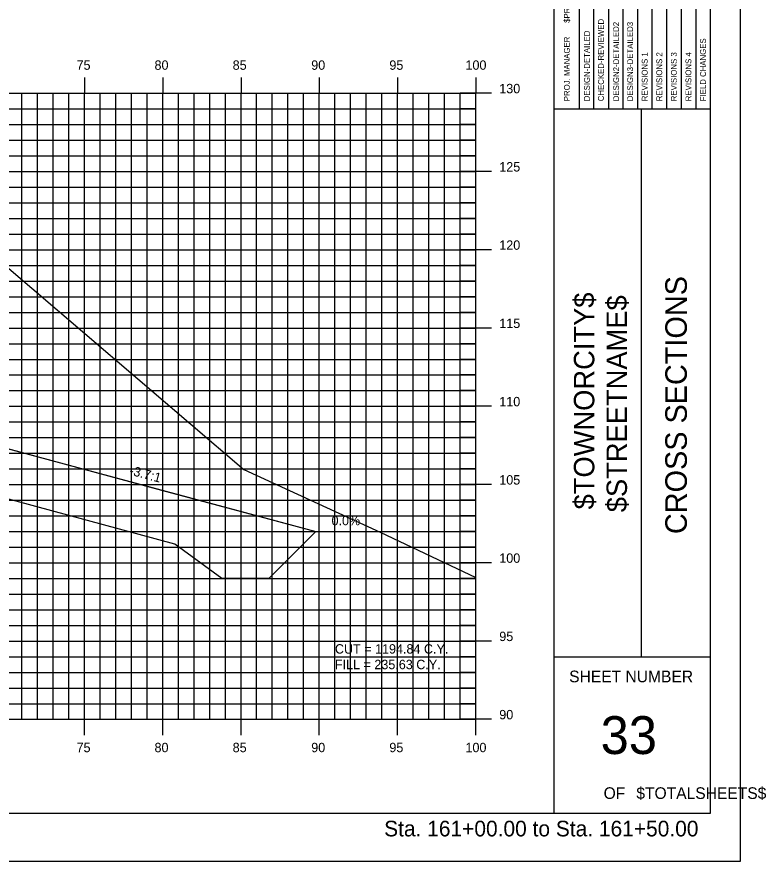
# Model space of a CAD drawing. Extents: x 850598 to 870284, y 366541 to 366651.
# Drawn here: x 853826.2 to 853874, y 366541.2 to 366595.1 of the extents above; entities that cross this region are included whole.
import ezdxf

# ---------------------------------------------------------------- set-up
doc = ezdxf.new("R2010")
doc.units = 0
for name, color, linetype in [('ANNOTATION', 7, 'Continuous'), ('BORDER', 7, 'Continuous'), ('D_Drainage_RipRap', 7, 'Continuous'), ('D_Roadway_Centerline', 7, 'Continuous'), ('D_Roadway_SlopeLines', 7, 'Continuous'), ('D_Text_Standard', 7, 'Continuous'), ('H_V ANNOTATION', 7, 'Continuous'), ('HIGHWAY_TITLE', 7, 'Continuous'), ('MAJOR', 7, 'Continuous'), ('MINOR', 7, 'Continuous'), ('PLOT BOUNDARY', 7, 'Continuous'), ('S_Roadway_Centerline', 7, 'Continuous')]:
    doc.layers.add(name, color=color, linetype=linetype)

msp = doc.modelspace()

# ---------------------------------------------------------------- linework, layer by layer
at = {"layer": 'BORDER'}
for p, q in [((853860.489, 366544.225), (853860.489, 366649.225)), ((853870.489, 366544.225), (853870.489, 366649.225)), ((853860.489, 366589.228), (853870.489, 366589.228)), ((853866.08, 366554.228), (853866.08, 366589.228)), ((853860.489, 366554.228), (853870.489, 366554.228)), ((853710.489, 366544.225), (853870.489, 366544.225))]:
    msp.add_line(p, q, dxfattribs=at)
for points in [[(853863.036, 366589.231), (853863.036, 366606.728)], [(853863.968, 366606.728), (853863.968, 366589.231)], [(853864.9, 366589.231), (853864.9, 366606.728)], [(853865.831, 366589.231), (853865.831, 366606.728)], [(853866.763, 366589.231), (853866.763, 366606.728)], [(853867.695, 366589.231), (853867.695, 366606.728)], [(853868.626, 366589.231), (853868.626, 366606.728)], [(853869.558, 366589.231), (853869.558, 366606.728)], [(853862.105, 366589.231), (853862.105, 366606.022)]]:
    msp.add_lwpolyline(points, dxfattribs=at)
at = {"layer": 'D_Drainage_RipRap'}
msp.add_lwpolyline([(853822.953, 366568.225), (853835.405, 366564.877), (853845.267, 366562.225), (853842.267, 366559.225), (853839.267, 366559.225), (853836.267, 366561.427), (853823.815, 366564.775), (853822.953, 366566.725), (853778.489, 366578.682), (853778.489, 366580.182)], close=True, dxfattribs=at)
at = {"layer": 'D_Roadway_Centerline'}
msp.add_lwpolyline([(853725.548, 366577.322), (853730.489, 366578.969), (853734.291, 366580.236), (853740.489, 366582.302), (853744.489, 366582.542), (853755.489, 366582.872), (853766.489, 366582.542), (853770.489, 366582.302), (853772.489, 366582.182), (853778.489, 366580.182), (853822.953, 366568.225), (853835.405, 366564.877), (853845.267, 366562.225), (853849.267, 366562.225)], dxfattribs=at)
at = {"layer": 'D_Roadway_SlopeLines'}
msp.add_lwpolyline([(853778.489, 366580.182), (853845.267, 366562.225), (853845.267, 366562.225)], dxfattribs=at)
at = {"layer": 'MAJOR'}
for p, q in [((853830.489, 366591.227), (853830.489, 366590.225)), ((853830.489, 366591.227), (853830.489, 366590.225)), ((853835.489, 366591.227), (853835.489, 366590.225)), ((853835.489, 366591.227), (853835.489, 366590.225)), ((853840.489, 366591.227), (853840.489, 366590.225)), ((853840.489, 366591.227), (853840.489, 366590.225)), ((853845.489, 366591.227), (853845.489, 366590.225)), ((853845.489, 366591.227), (853845.489, 366590.225)), ((853850.489, 366591.227), (853850.489, 366590.225)), ((853850.489, 366591.227), (853850.489, 366590.225)), ((853855.489, 366591.227), (853855.489, 366590.225)), ((853855.489, 366591.227), (853855.489, 366590.225)), ((853715.489, 366590.225), (853855.489, 366590.225)), ((853715.489, 366590.225), (853855.489, 366590.225)), ((853715.489, 366590.225), (853855.489, 366590.225)), ((853715.489, 366590.225), (853855.489, 366590.225)), ((853830.489, 366550.225), (853830.489, 366590.225)), ((853830.489, 366550.225), (853830.489, 366590.225)), ((853835.489, 366550.225), (853835.489, 366590.225)), ((853835.489, 366550.225), (853835.489, 366590.225)), ((853840.489, 366550.225), (853840.489, 366590.225)), ((853840.489, 366550.225), (853840.489, 366590.225)), ((853845.489, 366550.225), (853845.489, 366590.225)), ((853845.489, 366550.225), (853845.489, 366590.225)), ((853850.489, 366550.225), (853850.489, 366590.225)), ((853850.489, 366550.225), (853850.489, 366590.225)), ((853856.491, 366590.225), (853854.487, 366590.225)), ((853856.491, 366590.225), (853854.487, 366590.225)), ((853855.489, 366550.225), (853855.489, 366590.225)), ((853855.489, 366550.225), (853855.489, 366590.225)), ((853855.489, 366550.225), (853855.489, 366590.225)), ((853855.489, 366550.225), (853855.489, 366590.225)), ((853715.489, 366585.225), (853855.489, 366585.225)), ((853715.489, 366585.225), (853855.489, 366585.225)), ((853856.491, 366585.225), (853854.487, 366585.225)), ((853856.491, 366585.225), (853854.487, 366585.225)), ((853715.489, 366580.225), (853855.489, 366580.225)), ((853715.489, 366580.225), (853855.489, 366580.225)), ((853856.491, 366580.225), (853854.487, 366580.225)), ((853856.491, 366580.225), (853854.487, 366580.225)), ((853715.489, 366575.225), (853855.489, 366575.225)), ((853715.489, 366575.225), (853855.489, 366575.225)), ((853856.491, 366575.225), (853854.487, 366575.225)), ((853856.491, 366575.225), (853854.487, 366575.225)), ((853715.489, 366570.225), (853855.489, 366570.225)), ((853715.489, 366570.225), (853855.489, 366570.225)), ((853856.491, 366570.225), (853854.487, 366570.225)), ((853856.491, 366570.225), (853854.487, 366570.225)), ((853715.489, 366565.225), (853855.489, 366565.225)), ((853715.489, 366565.225), (853855.489, 366565.225)), ((853856.491, 366565.225), (853854.487, 366565.225)), ((853856.491, 366565.225), (853854.487, 366565.225)), ((853715.489, 366560.225), (853855.489, 366560.225)), ((853715.489, 366560.225), (853855.489, 366560.225)), ((853856.491, 366560.225), (853854.487, 366560.225)), ((853856.491, 366560.225), (853854.487, 366560.225)), ((853715.489, 366555.225), (853855.489, 366555.225)), ((853715.489, 366555.225), (853855.489, 366555.225)), ((853856.491, 366555.225), (853854.487, 366555.225)), ((853856.491, 366555.225), (853854.487, 366555.225)), ((853715.489, 366550.225), (853855.489, 366550.225)), ((853715.489, 366550.225), (853855.489, 366550.225)), ((853715.489, 366550.225), (853855.489, 366550.225)), ((853715.489, 366550.225), (853855.489, 366550.225)), ((853830.489, 366549.223), (853830.489, 366550.225)), ((853830.489, 366549.223), (853830.489, 366550.225)), ((853835.489, 366549.223), (853835.489, 366550.225)), ((853835.489, 366549.223), (853835.489, 366550.225)), ((853840.489, 366549.223), (853840.489, 366550.225)), ((853840.489, 366549.223), (853840.489, 366550.225)), ((853845.489, 366549.223), (853845.489, 366550.225)), ((853845.489, 366549.223), (853845.489, 366550.225)), ((853850.489, 366549.223), (853850.489, 366550.225)), ((853850.489, 366549.223), (853850.489, 366550.225)), ((853856.491, 366550.225), (853854.487, 366550.225)), ((853856.491, 366550.225), (853854.487, 366550.225)), ((853855.489, 366549.223), (853855.489, 366550.225)), ((853855.489, 366549.223), (853855.489, 366550.225))]:
    msp.add_line(p, q, dxfattribs=at)
at = {"layer": 'MINOR'}
for p, q in [((853826.489, 366550.225), (853826.489, 366590.225)), ((853826.489, 366550.225), (853826.489, 366590.225)), ((853827.489, 366550.225), (853827.489, 366590.225)), ((853827.489, 366550.225), (853827.489, 366590.225)), ((853828.489, 366550.225), (853828.489, 366590.225)), ((853828.489, 366550.225), (853828.489, 366590.225)), ((853829.489, 366550.225), (853829.489, 366590.225)), ((853829.489, 366550.225), (853829.489, 366590.225)), ((853831.489, 366550.225), (853831.489, 366590.225)), ((853831.489, 366550.225), (853831.489, 366590.225)), ((853832.489, 366550.225), (853832.489, 366590.225)), ((853832.489, 366550.225), (853832.489, 366590.225)), ((853833.489, 366550.225), (853833.489, 366590.225)), ((853833.489, 366550.225), (853833.489, 366590.225)), ((853834.489, 366550.225), (853834.489, 366590.225)), ((853834.489, 366550.225), (853834.489, 366590.225)), ((853836.489, 366550.225), (853836.489, 366590.225)), ((853836.489, 366550.225), (853836.489, 366590.225)), ((853837.489, 366550.225), (853837.489, 366590.225)), ((853837.489, 366550.225), (853837.489, 366590.225)), ((853838.489, 366550.225), (853838.489, 366590.225)), ((853838.489, 366550.225), (853838.489, 366590.225)), ((853839.489, 366550.225), (853839.489, 366590.225)), ((853839.489, 366550.225), (853839.489, 366590.225)), ((853841.489, 366550.225), (853841.489, 366590.225)), ((853841.489, 366550.225), (853841.489, 366590.225)), ((853842.489, 366550.225), (853842.489, 366590.225)), ((853842.489, 366550.225), (853842.489, 366590.225)), ((853843.489, 366550.225), (853843.489, 366590.225)), ((853843.489, 366550.225), (853843.489, 366590.225)), ((853844.489, 366550.225), (853844.489, 366590.225)), ((853844.489, 366550.225), (853844.489, 366590.225)), ((853846.489, 366550.225), (853846.489, 366590.225)), ((853846.489, 366550.225), (853846.489, 366590.225)), ((853847.489, 366550.225), (853847.489, 366590.225)), ((853847.489, 366550.225), (853847.489, 366590.225)), ((853848.489, 366550.225), (853848.489, 366590.225)), ((853848.489, 366550.225), (853848.489, 366590.225)), ((853849.489, 366550.225), (853849.489, 366590.225)), ((853849.489, 366550.225), (853849.489, 366590.225)), ((853851.489, 366550.225), (853851.489, 366590.225)), ((853851.489, 366550.225), (853851.489, 366590.225)), ((853852.489, 366550.225), (853852.489, 366590.225)), ((853852.489, 366550.225), (853852.489, 366590.225)), ((853853.489, 366550.225), (853853.489, 366590.225)), ((853853.489, 366550.225), (853853.489, 366590.225)), ((853854.489, 366550.225), (853854.489, 366590.225)), ((853854.489, 366550.225), (853854.489, 366590.225)), ((853715.489, 366589.225), (853855.489, 366589.225)), ((853715.489, 366589.225), (853855.489, 366589.225)), ((853855.489, 366589.225), (853854.487, 366589.225)), ((853855.489, 366589.225), (853854.487, 366589.225)), ((853715.489, 366588.225), (853855.489, 366588.225)), ((853715.489, 366588.225), (853855.489, 366588.225)), ((853855.489, 366588.225), (853854.487, 366588.225)), ((853855.489, 366588.225), (853854.487, 366588.225)), ((853715.489, 366587.225), (853855.489, 366587.225)), ((853715.489, 366587.225), (853855.489, 366587.225)), ((853855.489, 366587.225), (853854.487, 366587.225)), ((853855.489, 366587.225), (853854.487, 366587.225)), ((853715.489, 366586.225), (853855.489, 366586.225)), ((853715.489, 366586.225), (853855.489, 366586.225)), ((853855.489, 366586.225), (853854.487, 366586.225)), ((853855.489, 366586.225), (853854.487, 366586.225)), ((853715.489, 366584.225), (853855.489, 366584.225)), ((853715.489, 366584.225), (853855.489, 366584.225)), ((853855.489, 366584.225), (853854.487, 366584.225)), ((853855.489, 366584.225), (853854.487, 366584.225)), ((853715.489, 366583.225), (853855.489, 366583.225)), ((853715.489, 366583.225), (853855.489, 366583.225)), ((853855.489, 366583.225), (853854.487, 366583.225)), ((853855.489, 366583.225), (853854.487, 366583.225)), ((853715.489, 366582.225), (853855.489, 366582.225)), ((853715.489, 366582.225), (853855.489, 366582.225)), ((853855.489, 366582.225), (853854.487, 366582.225)), ((853855.489, 366582.225), (853854.487, 366582.225)), ((853715.489, 366581.225), (853855.489, 366581.225)), ((853715.489, 366581.225), (853855.489, 366581.225)), ((853855.489, 366581.225), (853854.487, 366581.225)), ((853855.489, 366581.225), (853854.487, 366581.225)), ((853715.489, 366579.225), (853855.489, 366579.225)), ((853715.489, 366579.225), (853855.489, 366579.225)), ((853855.489, 366579.225), (853854.487, 366579.225)), ((853855.489, 366579.225), (853854.487, 366579.225)), ((853715.489, 366578.225), (853855.489, 366578.225)), ((853715.489, 366578.225), (853855.489, 366578.225)), ((853855.489, 366578.225), (853854.487, 366578.225)), ((853855.489, 366578.225), (853854.487, 366578.225)), ((853715.489, 366577.225), (853855.489, 366577.225)), ((853715.489, 366577.225), (853855.489, 366577.225)), ((853855.489, 366577.225), (853854.487, 366577.225)), ((853855.489, 366577.225), (853854.487, 366577.225)), ((853715.489, 366576.225), (853855.489, 366576.225)), ((853715.489, 366576.225), (853855.489, 366576.225)), ((853855.489, 366576.225), (853854.487, 366576.225)), ((853855.489, 366576.225), (853854.487, 366576.225)), ((853715.489, 366574.225), (853855.489, 366574.225)), ((853715.489, 366574.225), (853855.489, 366574.225)), ((853855.489, 366574.225), (853854.487, 366574.225)), ((853855.489, 366574.225), (853854.487, 366574.225)), ((853715.489, 366573.225), (853855.489, 366573.225)), ((853715.489, 366573.225), (853855.489, 366573.225)), ((853855.489, 366573.225), (853854.487, 366573.225)), ((853855.489, 366573.225), (853854.487, 366573.225)), ((853715.489, 366572.225), (853855.489, 366572.225)), ((853715.489, 366572.225), (853855.489, 366572.225)), ((853855.489, 366572.225), (853854.487, 366572.225)), ((853855.489, 366572.225), (853854.487, 366572.225)), ((853715.489, 366571.225), (853855.489, 366571.225)), ((853715.489, 366571.225), (853855.489, 366571.225)), ((853855.489, 366571.225), (853854.487, 366571.225)), ((853855.489, 366571.225), (853854.487, 366571.225)), ((853715.489, 366569.225), (853855.489, 366569.225)), ((853715.489, 366569.225), (853855.489, 366569.225)), ((853855.489, 366569.225), (853854.487, 366569.225)), ((853855.489, 366569.225), (853854.487, 366569.225)), ((853715.489, 366568.225), (853855.489, 366568.225)), ((853715.489, 366568.225), (853855.489, 366568.225)), ((853855.489, 366568.225), (853854.487, 366568.225)), ((853855.489, 366568.225), (853854.487, 366568.225)), ((853715.489, 366567.225), (853855.489, 366567.225)), ((853715.489, 366567.225), (853855.489, 366567.225)), ((853855.489, 366567.225), (853854.487, 366567.225)), ((853855.489, 366567.225), (853854.487, 366567.225)), ((853715.489, 366566.225), (853855.489, 366566.225)), ((853715.489, 366566.225), (853855.489, 366566.225)), ((853855.489, 366566.225), (853854.487, 366566.225)), ((853855.489, 366566.225), (853854.487, 366566.225)), ((853715.489, 366564.225), (853855.489, 366564.225)), ((853715.489, 366564.225), (853855.489, 366564.225)), ((853855.489, 366564.225), (853854.487, 366564.225)), ((853855.489, 366564.225), (853854.487, 366564.225)), ((853715.489, 366563.225), (853855.489, 366563.225)), ((853715.489, 366563.225), (853855.489, 366563.225)), ((853855.489, 366563.225), (853854.487, 366563.225)), ((853855.489, 366563.225), (853854.487, 366563.225)), ((853715.489, 366562.225), (853855.489, 366562.225)), ((853715.489, 366562.225), (853855.489, 366562.225)), ((853855.489, 366562.225), (853854.487, 366562.225)), ((853855.489, 366562.225), (853854.487, 366562.225)), ((853715.489, 366561.225), (853855.489, 366561.225)), ((853715.489, 366561.225), (853855.489, 366561.225)), ((853855.489, 366561.225), (853854.487, 366561.225)), ((853855.489, 366561.225), (853854.487, 366561.225)), ((853715.489, 366559.225), (853855.489, 366559.225)), ((853715.489, 366559.225), (853855.489, 366559.225)), ((853855.489, 366559.225), (853854.487, 366559.225)), ((853855.489, 366559.225), (853854.487, 366559.225)), ((853715.489, 366558.225), (853855.489, 366558.225)), ((853715.489, 366558.225), (853855.489, 366558.225)), ((853855.489, 366558.225), (853854.487, 366558.225)), ((853855.489, 366558.225), (853854.487, 366558.225)), ((853715.489, 366557.225), (853855.489, 366557.225)), ((853715.489, 366557.225), (853855.489, 366557.225)), ((853855.489, 366557.225), (853854.487, 366557.225)), ((853855.489, 366557.225), (853854.487, 366557.225)), ((853715.489, 366556.225), (853855.489, 366556.225)), ((853715.489, 366556.225), (853855.489, 366556.225)), ((853855.489, 366556.225), (853854.487, 366556.225)), ((853855.489, 366556.225), (853854.487, 366556.225)), ((853715.489, 366554.225), (853855.489, 366554.225)), ((853715.489, 366554.225), (853855.489, 366554.225)), ((853855.489, 366554.225), (853854.487, 366554.225)), ((853855.489, 366554.225), (853854.487, 366554.225)), ((853715.489, 366553.225), (853855.489, 366553.225)), ((853715.489, 366553.225), (853855.489, 366553.225)), ((853855.489, 366553.225), (853854.487, 366553.225)), ((853855.489, 366553.225), (853854.487, 366553.225)), ((853715.489, 366552.225), (853855.489, 366552.225)), ((853715.489, 366552.225), (853855.489, 366552.225)), ((853855.489, 366552.225), (853854.487, 366552.225)), ((853855.489, 366552.225), (853854.487, 366552.225)), ((853715.489, 366551.225), (853855.489, 366551.225)), ((853715.489, 366551.225), (853855.489, 366551.225)), ((853855.489, 366551.225), (853854.487, 366551.225)), ((853855.489, 366551.225), (853854.487, 366551.225))]:
    msp.add_line(p, q, dxfattribs=at)
at = {"layer": 'PLOT BOUNDARY'}
msp.add_lwpolyline([(853702.395, 366541.166), (853872.395, 366541.166), (853872.395, 366651.166), (853702.395, 366651.166)], close=True, dxfattribs=at)
at = {"layer": 'S_Roadway_Centerline'}
msp.add_lwpolyline([(853715.489, 366577.258), (853727.93, 366577.337), (853739.322, 366577.409), (853747.757, 366577.946), (853775.869, 366579.776), (853785.205, 366581.53), (853785.911, 366581.674), (853786.364, 366581.76), (853788.576, 366582.055), (853789.791, 366582.106), (853803.328, 366582.644), (853805.352, 366582.582), (853819.384, 366582.138), (853823.386, 366580.873), (853823.494, 366580.831), (853823.71, 366580.659), (853840.663, 366566.181), (853849.375, 366562.176), (853855.489, 366559.284)], dxfattribs=at)

# ---------------------------------------------------------------- texts
at = {"layer": 'ANNOTATION'}
msp.add_text('-3.7:1', height=0.6, rotation=344.9493, dxfattribs=at).set_placement((853833.314, 366565.875))
msp.add_text('0.0%', height=0.6, dxfattribs=at).set_placement((853846.272, 366562.625))
at = {"layer": 'BORDER'}
for s, height, rotation, p in [('$PROJMANAGER$', 0.37275, 90, (853861.493, 366594.723)), ('CHECKED-REVIEWED', 0.37275, 90, (853863.67, 366589.716)), ('DESIGN2-DETAILED2', 0.37275, 90, (853864.639, 366589.716)), ('DESIGN3-DETAILED3', 0.37275, 90, (853865.533, 366589.716)), ('PROJ. MANAGER', 0.37275, 90, (853861.493, 366589.716)), ('DESIGN-DETAILED', 0.37275, 90, (853862.775, 366589.716)), ('FIELD CHANGES', 0.37275, 90, (853870.192, 366589.716)), ('REVISIONS 1', 0.37275, 90, (853866.465, 366589.716)), ('REVISIONS 2', 0.37275, 90, (853867.396, 366589.716)), ('REVISIONS 3', 0.37275, 90, (853868.328, 366589.716)), ('REVISIONS 4', 0.37275, 90, (853869.26, 366589.716)), ('CROSS SECTIONS', 1.37787, 90, (853868.973, 366562.062)), ('SHEET NUMBER', 0.74527, 360, (853861.454, 366552.592)), ('33', 2.4194, 360, (853863.464, 366548.008)), ('OF', 0.7453, 360, (853863.656, 366545.138)), ('$TOTALSHEETS$', 0.74527, 360, (853865.745, 366545.138))]:
    msp.add_text(s, height=height, rotation=rotation, dxfattribs=at).set_placement(p)
at = {"layer": 'D_Text_Standard'}
for s, p in [('CUT = 1194.84 C.Y.', (853846.489, 366554.425)), ('FILL = 235.63 C.Y.', (853846.489, 366553.429))]:
    msp.add_text(s, height=0.6, dxfattribs=at).set_placement(p)
at = {"layer": 'H_V ANNOTATION'}
for s, height, p in [('75', 0.6, (853829.983, 366591.725)), ('80', 0.6, (853834.964, 366591.725)), ('85', 0.6, (853839.956, 366591.725)), ('90', 0.6, (853844.975, 366591.725)), ('95', 0.6, (853849.967, 366591.725)), ('100', 0.6, (853854.83, 366591.725)), ('130', 0.6, (853856.989, 366590.225)), ('125', 0.6, (853856.989, 366585.225)), ('120', 0.6, (853856.989, 366580.225)), ('115', 0.6, (853856.989, 366575.225)), ('110', 0.6, (853856.989, 366570.225)), ('105', 0.6, (853856.989, 366565.225)), ('100', 0.6, (853856.989, 366560.225)), ('95', 0.6, (853856.989, 366555.225)), ('90', 0.6, (853856.989, 366550.225)), ('75', 0.6, (853829.983, 366548.125)), ('80', 0.6, (853834.964, 366548.125)), ('85', 0.6, (853839.956, 366548.125)), ('90', 0.6, (853844.975, 366548.125)), ('95', 0.6, (853849.967, 366548.125)), ('100', 0.6, (853854.83, 366548.125)), ('Sta. 161+00.00 to Sta. 161+50.00', 1.0002, (853849.634, 366542.745))]:
    msp.add_text(s, height=height, dxfattribs=at).set_placement(p)
at = {"layer": 'HIGHWAY_TITLE'}
for s, p in [('$TOWNORCITY$', (853863.061, 366563.637)), ('$STREETNAME$', (853865.148, 366563.457))]:
    msp.add_text(s, height=1.30428, rotation=90, dxfattribs=at).set_placement(p)

doc.saveas('drawing.dxf')
